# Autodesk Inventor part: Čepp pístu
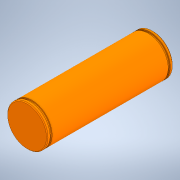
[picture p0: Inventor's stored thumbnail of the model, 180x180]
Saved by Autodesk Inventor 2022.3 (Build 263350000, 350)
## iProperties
Created: 2025-11
Part Number: Čepp pístu
Material: Všeobecné
Document SubType Name: Modeling
Designer: Hra42
Density: 1 g/cm^3
Appearance: Výchozí(1)
Author: Hra42
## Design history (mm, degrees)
sketch "Náčrt1"
  geometry: C1 r 12.7 at (0, 0); 1 further point
  constraints: 1 centre point, 1 coincident
  dimensions: "d0" = 25.4 diameter of C1
extrude "Vysunutí1" new body sketch "Náčrt1" distance "d1" = 79.3; taper "d2" = 0 deg
sketch "Náčrt2"
  geometry: L1 (12.7, 0)-(12.7, 79.3) reference; L2 (12.7, 1.8)-(12, 1.8); L3 (12, 1.8)-(12, 3.1); L4 (12, 3.1)-(12.7, 3.1); L5 (12.7, 0)-(-12.7, 0) reference; L6 (0, -15.86)-(0, 95.16) reference; L7 (12.7, 0)-(12.7, 79.3) reference; L8 (12.7, 39.65)-(-12.7, 39.65); L9 (-12.7, 0)-(-12.7, 79.3) reference; L10 (12.7, 77.5)-(12, 77.5); L11 (12, 77.5)-(12, 76.2); L12 (12, 76.2)-(12.7, 76.2); 3 further points
  constraints: 14 end point, 4 symmetric about line, 2 midpoint, 2 perpendicular, 2 point on line, 1 horizontal
  dimensions: "d3" = 1.8 distance between parallel lines of L5 L2; "d4" = 1.3 distance between parallel lines of L4 L2; "d5" = 0.7 distance of L3.end L4.end
revolve "Rotace1" sketch "Náčrt2" stored, may be unused: angle "d6" = 360 deg
chamfer "Zkosení1" distance "d7" = 0.5; stored, may be unused: second distance "d8" = 2, angle "d9" = 45 deg
node "Těleso1"
